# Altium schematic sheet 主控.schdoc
size 420 x 297 mm; Symbol: Drawing-Symbol_A4; Company: 嘉立创EDA; Version: V1.0; Page Size: A4; @Project Name: FOC; @Update Date: 2026-07-20; @Create Date: 2026-07-20; Device: Drawing-Symbol_A4; @Board Name: Board1; @Page Name: P1; @Create Time: 00:30:57; @Page Count: 3; @Page No: 3; @Schematic Name: Schematic1; @Update Time: 00:30:57; @Assembly Variant: Basic; Border: 1; Title Block Position: 3; Size: A4; Width: 1655; Height: 1170; Region Start: 1; X Region Count: 6; Y Region Count: 4; Blade Width: 10
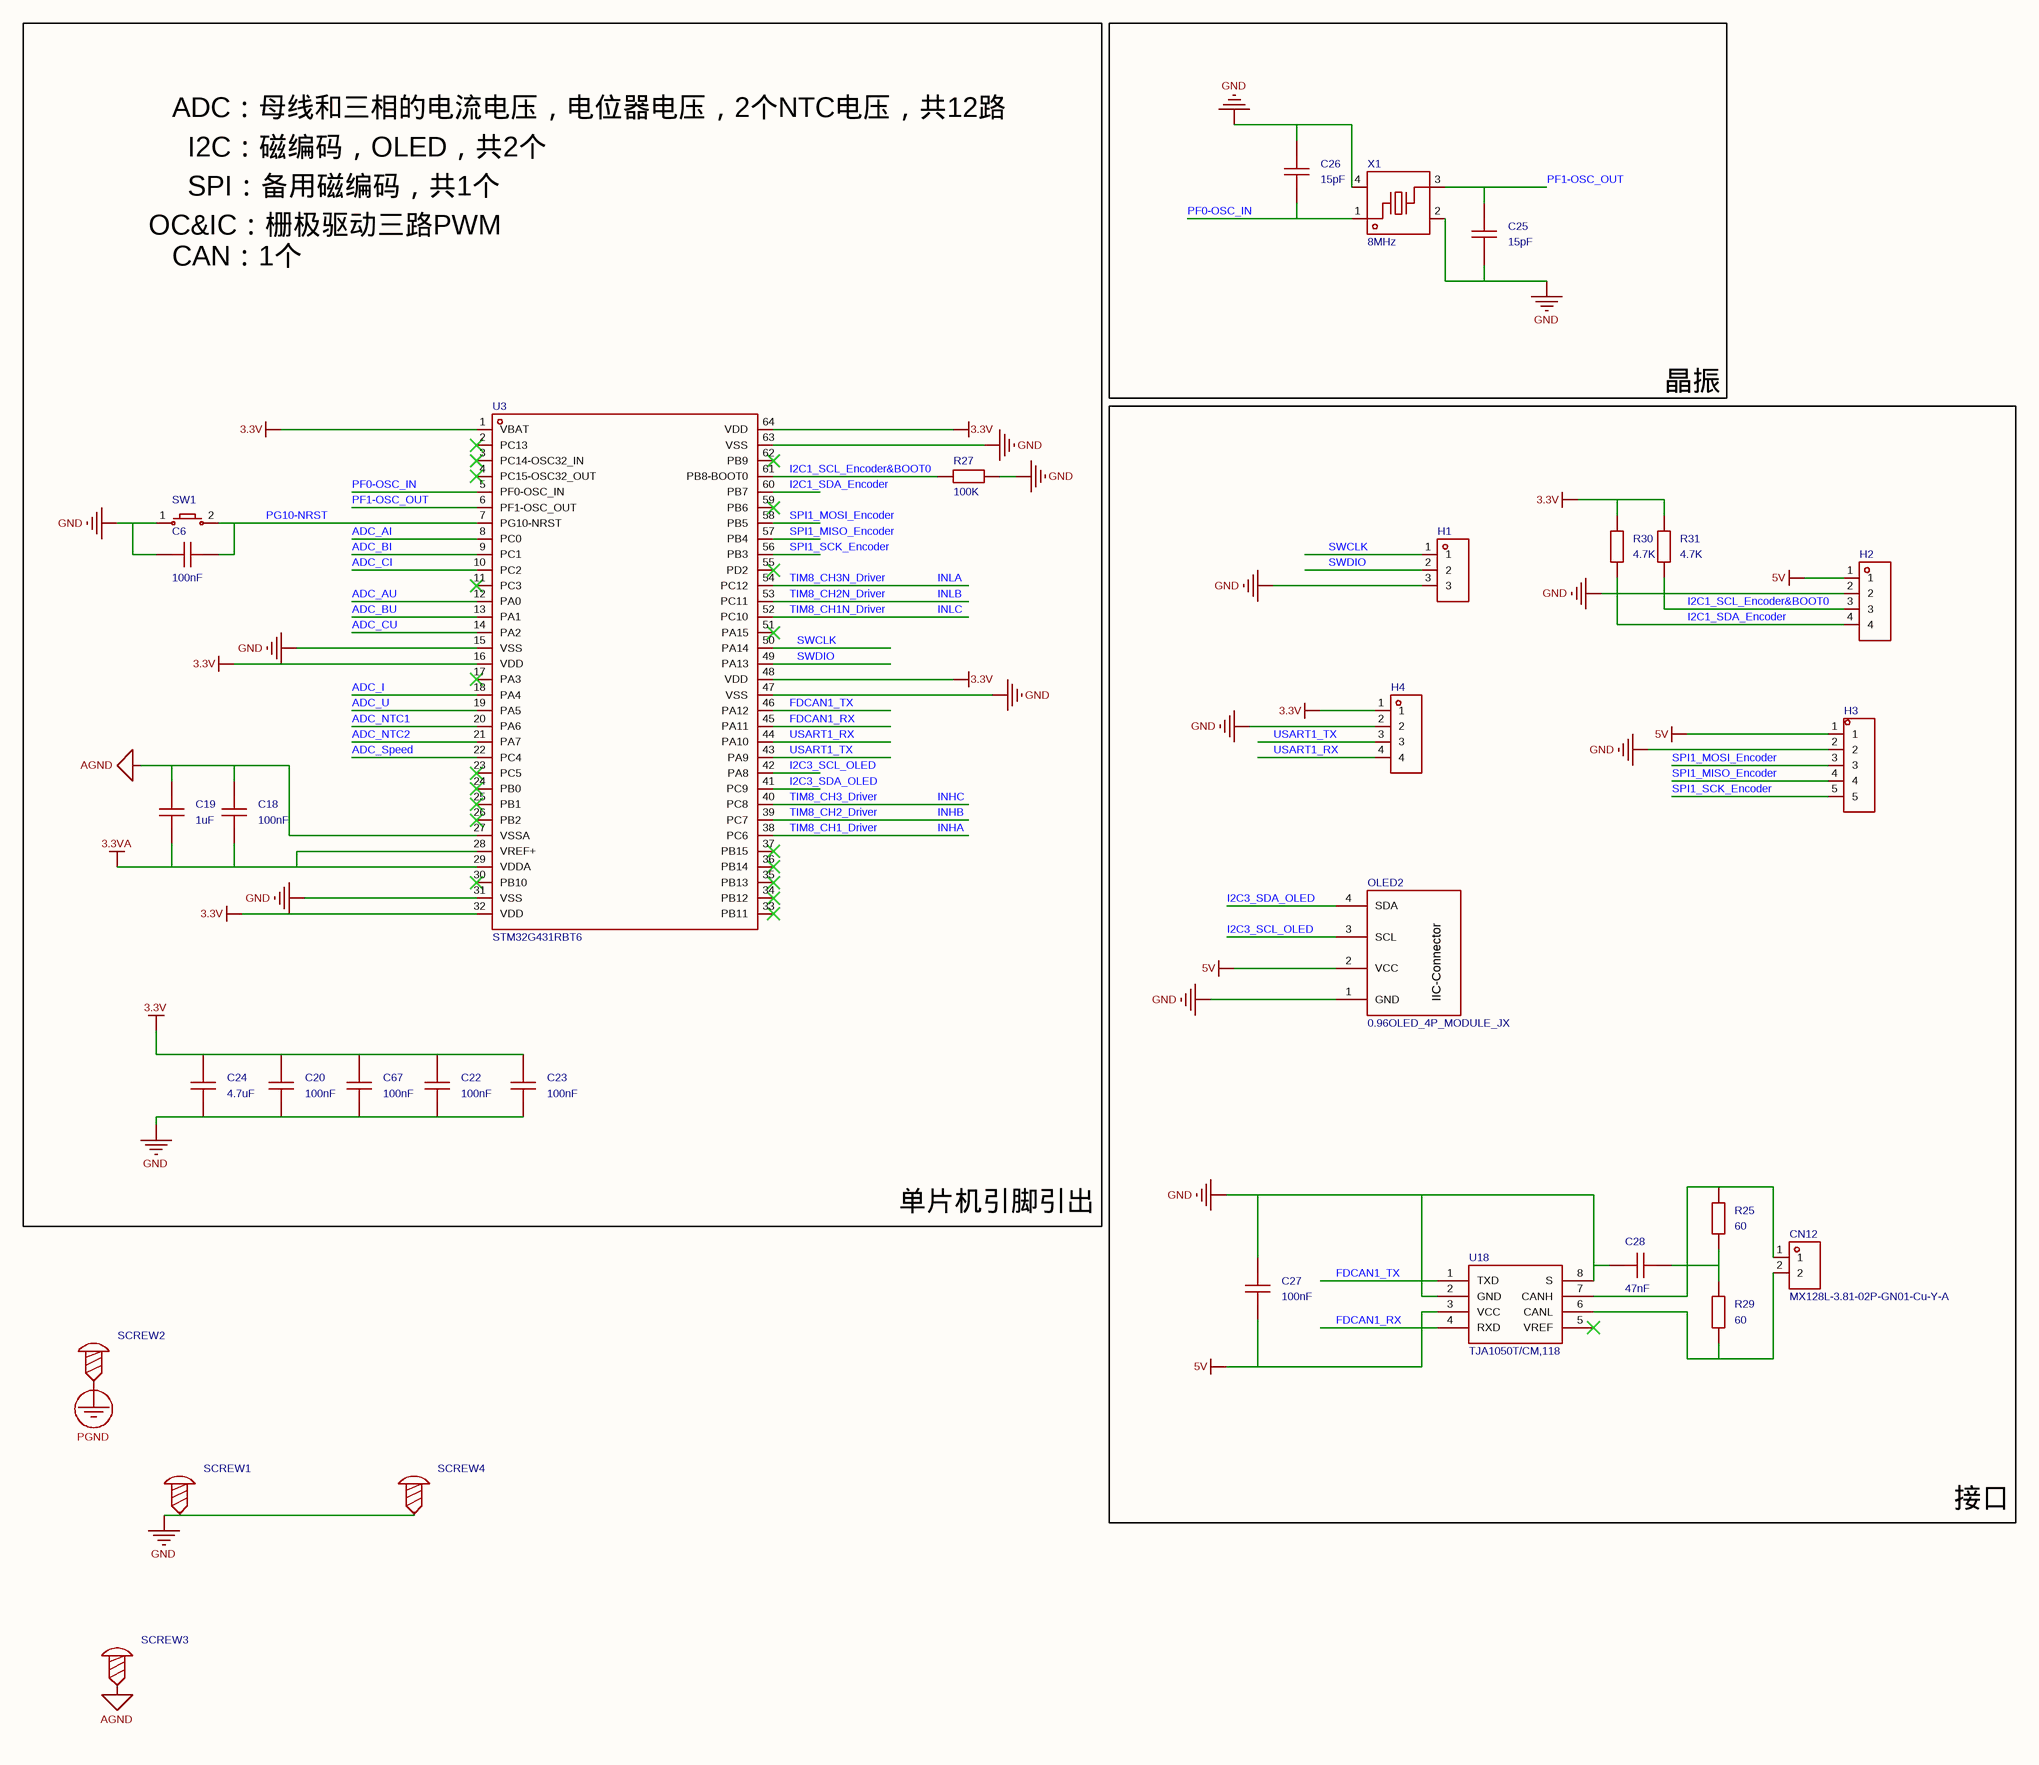
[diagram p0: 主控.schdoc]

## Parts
C6  100nF  [C0603]
C18  100nF  [C0603]
C19  1uF  [C0603]
C20  100nF  [C0603]
C22  100nF  [C0603]
C23  100nF  [C0603]
C24  4.7uF  [C0603]
C25  15pF  [C0603]
C26  15pF  [C0603]
C27  100nF  [C0603]
C28  47nF  [C0603]
C67  100nF  [C0603]
CN12  MX128L-3.81-02P-GN01-Cu-Y-A  [CONN-TH_2P-P3.81_MX128L-3.81-GN01-02P-CU-Y-A]
H1  (no value)  [HDR-TH_3P-P2.54-V-M]
H2  (no value)  [HDR-TH_4P-P2.54-V-M]
H3  (no value)  [HDR-TH_5P-P2.54-V-M]
H4  (no value)  [HDR-TH_4P-P2.54-V-M]
OLED2  0.96OLED_4P_MODULE_JX  [0.96OLED_4P]
R25  60  [R0603]
R27  100K  [R0603]
R29  60  [R0603]
R30  4.7K  [R0603]
R31  4.7K  [R0603]
SCREW1  (no value)  [M3螺丝]
SCREW2  (no value)  [M3螺丝]
SCREW3  (no value)  [M3螺丝]
SCREW4  (no value)  [M3螺丝]
SW1  (no value)  [Key_SMD_3x4x2]
U3  STM32G431RBT6  [LQFP-64_L10.0-W10.0-P0.50-LS12.0-BL]
U18  TJA1050T/CM,118  [SOIC-8_L5.0-W4.0-P1.27-LS6.0-BL]
X1  8MHz  [CRYSTAL-SMD_4P-L3.2-W2.5-BL-1]

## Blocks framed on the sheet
晶振: C25 C26 X1
接口: C27 C28 CN12 H1-H4 OLED2 R25 R29-R31 U18

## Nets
3.3V: C20.2 C22.2 C23.2 C24.2 C67.2 H4.1 R30.2 R31.2 U3.1(VBAT) U3.16(VDD) U3.32(VDD) U3.48(VDD) U3.64(VDD)
3.3VA: C18.1 C19.1 U3.28(VREF+) U3.29(VDDA)
5V: C27.2 H2.1 H3.1 OLED2.2(VCC) U18.3(VCC)
AGND: C18.2 C19.2 SCREW3.1 U3.27(VSSA)
GND: C6.1 C20.1 C22.1 C23.1 C24.1 C25.1 C26.2 C27.1 C28.1 C67.1 H1.3 H2.2 H3.2 H4.2 OLED2.1(GND) R27.2 SCREW1.1 SCREW4.1 SW1.1 U3.15(VSS) U3.31(VSS) U3.47(VSS) U3.63(VSS) U18.2(GND) U18.8(S) X1.2(GND) X1.4(GND)
PGND: SCREW2.1
ADC_AI: U3.8(PC0)
ADC_AU: U3.12(PA0)
ADC_BI: U3.9(PC1)
ADC_BU: U3.13(PA1)
ADC_CI: U3.10(PC2)
ADC_CU: U3.14(PA2)
ADC_I: U3.18(PA4)
ADC_NTC1: U3.20(PA6)
ADC_NTC2: U3.21(PA7)
ADC_Speed: U3.22(PC4)
ADC_U: U3.19(PA5)
FDCAN1_RX: U3.45(PA11) U18.4(RXD)
FDCAN1_TX: U3.46(PA12) U18.1(TXD)
I2C1_SCL_Encoder&BOOT0: H2.3 R27.1 R31.1 U3.61(PB8-BOOT0)
I2C1_SDA_Encoder: H2.4 R30.1 U3.60(PB7)
I2C3_SCL_OLED: OLED2.3(SCL) U3.42(PA8)
I2C3_SDA_OLED: OLED2.4(SDA) U3.41(PC9)
INHA: U3.38(PC6)  [also labelled TIM8_CH1_Driver]
INHB: U3.39(PC7)  [also labelled TIM8_CH2_Driver]
INHC: U3.40(PC8)  [also labelled TIM8_CH3_Driver]
INLA: U3.54(PC12)  [also labelled TIM8_CH3N_Driver]
INLB: U3.53(PC11)  [also labelled TIM8_CH2N_Driver]
INLC: U3.52(PC10)  [also labelled TIM8_CH1N_Driver]
PF0-OSC_IN: C26.1 U3.5(PF0-OSC_IN) X1.1
PF1-OSC_OUT: C25.2 U3.6(PF1-OSC_OUT) X1.3
PG10-NRST: C6.2 SW1.2 U3.7(PG10-NRST)
SPI1_MISO_Encoder: H3.4 U3.57(PB4)
SPI1_MOSI_Encoder: H3.3 U3.58(PB5)
SPI1_SCK_Encoder: H3.5 U3.56(PB3)
SWCLK: H1.1 U3.50(PA14)
SWDIO: H1.2 U3.49(PA13)
USART1_RX: H4.4 U3.44(PA10)
USART1_TX: H4.3 U3.43(PA9)
NetC28_2: C28.2 R25.1 R29.2
NetCN12_1: CN12.1 R25.2 U18.7(CANH)
NetCN12_2: CN12.2 R29.1 U18.6(CANL)

Not connected (* = marked no-connect by the designer): U3 2(PC13)* 3(PC14-OSC32_IN)* 4(PC15-OSC32_OUT)* 11(PC3)* 17(PA3)* 23(PC5)* 24(PB0)* 25(PB1)* 26(PB2)* 30(PB10)* 33(PB11)* 34(PB12)* 35(PB13)* 36(PB14)* 37(PB15)* 51(PA15)* 55(PD2)* 59(PB6)* 62(PB9)*; U18 5(VREF)*

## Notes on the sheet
- ADC：母线和三相的电流电压，电位器电压，2个NTC电压，共12路
- I2C：磁编码，OLED，共2个
- SPI：备用磁编码，共1个
- OC&IC：栅极驱动三路PWM
- CAN：1个
- 单片机引脚引出

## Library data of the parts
C6 C18-C20 C22-C28 C67 = CAP_0603: Symbol: Capacitance; 3D Model: ac125912035d415993ca9572d50418b10819f05c4eef4c71ace90d822a990e87; 3D Model Transform: 62.992,31.496,0,0,0,0,0,0,0; ConvertToPcb: yes; ModelName: C0603_L1.6-W0.8-H0.8
CN12 = MX128L-3.81-02P-GN01-Cu-Y-A: 结构:1x2P;间距:3.81mm;颜色:绿色;安装方式:直插;排数:1;每排PIN数:2;额定电流:10A;额定电压:150V;线规 - AWG:16~26;线规 - 平方毫米:1.5;工作温度范围:-40℃~+105℃;; Manufacturer: MAX(迈旭); Symbol: MX128L-3.81-GN01-02P-CU-Y-A; 3D Model: 3ada76795bf04056bedcd0ec9f9046df0819f05c4eef4c71ace90d822a990e87; 3D Model Transform: 300.3931,291.338,0,0,0,0,0,-11.811,-137.795; Structure: 1x2P; Pitch: 3.81mm; Number of PINs Per Row: 2; Screw Specification: M2; Current Rating (Max): 10A; Voltage Rating (Max): 150V; Wire Gauge - AWG: 16~26; Wire Gauge - mm2: 1.5; AddInBom: yes
H1 = HDR-M_2.54_1x3P: AddInBom: yes; ModelId: bb473b6d38ff42a99216a4fcdbdcc4cb0819f05c4eef4c71ace90d822a990e87; ModelName: HDR-TH_3P-P2.54-M-LI-1X3P; ModelTransform: 300.03877,100,0,0,0,0,0,0,-118.11
H2 = HDR-M_2.54_1x4P: Symbol: PZ254V-11-04P; ConvertToPcb: yes; ModelId: 112f4d05e8d64e99ab9a333894bea4f90819f05c4eef4c71ace90d822a990e87; ModelName: HDR-TH_4P-P2.54-M-LI-1X4P; ModelTransform: 399.999,104.7242,0,0,0,0,0,0,-118.11
H3 = HDR-M_2.54_1x5P: Symbol: MTP125-1105S1; ConvertToPcb: yes; ModelId: 47d466e4a34f4fc5bc626cf773a24dd50819f05c4eef4c71ace90d822a990e87; ModelName: HDR-TH_5P-P2.54-M-LI-1X5P; ModelTransform: 499.999,100,0,0,0,0,0,0,-118.11
H4 = HDR-M_2.54_1x4P: Symbol: PZ254V-11-04P; 3D Model: 112f4d05e8d64e99ab9a333894bea4f90819f05c4eef4c71ace90d822a990e87; 3D Model Transform: 399.999,104.7242,0,0,0,0,0,0,-118.11; ConvertToPcb: yes; ModelName: HDR-TH_4P-P2.54-M-LI-1X4P
OLED2 = oled: AddInBom: yes; ModelId: 79c000fdb68d45a296c2e9bedf4f9055450f5ac3ad8e425faa0767b05d830c6d; ModelTransform: 1393.69792,1318.895,0,0,0,0,0,-560.079,-137.795
R25 R27 R29-R31 = Res_0603: Symbol: 电阻; 3D Model: fc143cca1e79419f9cd78b61e9279f080819f05c4eef4c71ace90d822a990e87; 3D Model Transform: 31.8897,63.7794,0,90,0,0,0,0,0; ConvertToPcb: yes
SCREW1-SCREW4 = M3螺丝: Symbol: 螺丝孔; ConvertToPcb: yes
SW1 = Key_SMD_3x4x2: Symbol: 轻触按键x2; ConvertToPcb: yes; ModelId: 63599cce708d48afbce1b0db003544770819f05c4eef4c71ace90d822a990e87; ModelName: SW-SMD_L4.0-W2.9-H2-LS5.0; ModelTransform: 196.85,114.17,79.13,0,0,0,0,0,0
U3 = STM32G431RBT6: CPU内核:ARM-M系列;CPU最大主频:170MHz;应用领域:-;; Manufacturer: ST(意法半导体); AddInBom: yes; ModelId: cd9de06618c44fcf82654c43a457f83c0819f05c4eef4c71ace90d822a990e87; ModelName: LQFP-64_L10.0-W10.0-H1.4-LS12.0-P0.50; ModelTransform: 472.441,472.441,0,0,0,0,0,0.465,0; CPU Maximum Speed: 170MHz; Program Storage Size: 128KB; Number of I/O: 52; ADC (Bit): 12bit; Voltage - Supply: 1.71V~3.6V
U18 = TJA1050T/CM,118: 类型:CAN收发器;数据速率:1Mbps;; Manufacturer: NXP(恩智浦); 3D Model: 7abc64c95a1a4a04a4ef38f9097c870b0819f05c4eef4c71ace90d822a990e87; 3D Model Transform: 192.913,236.22,0,0,0,0,0,0,0; Data Rate: 1Mbps; Voltage - Supply: 4.75V~5.25V; Current - Supply: 50mA; AddInBom: yes
X1 = XL2EL89COI-111YLC-8M: 晶振类型:贴片晶振;频率:8MHz;常温频差:±10ppm;负载电容:12pF;频率稳定度:±20ppm;; Manufacturer: YXC(扬兴晶振); AddInBom: yes; ModelId: 4495b492a02c4f389e505ec8ae3aaf1b0819f05c4eef4c71ace90d822a990e87; ModelTransform: 125.984,98.425,0,0,0,0,0,0,0; Normal temperature Frequency Tolerance: ±10ppm; Load Capacitance: 12pF; Frequency Stability: ±20ppm; Equivalent Series Resistance(ESR): 150Ω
